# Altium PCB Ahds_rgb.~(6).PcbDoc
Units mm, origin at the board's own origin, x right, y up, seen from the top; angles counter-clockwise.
Board outline 51.94 x 97.28 mm, 2 copper layers (Top Layer, Bottom Layer); 73 components, 40 nets, 226 pads, 0 vias.
Unrouted connection lines stored in the file: 180.
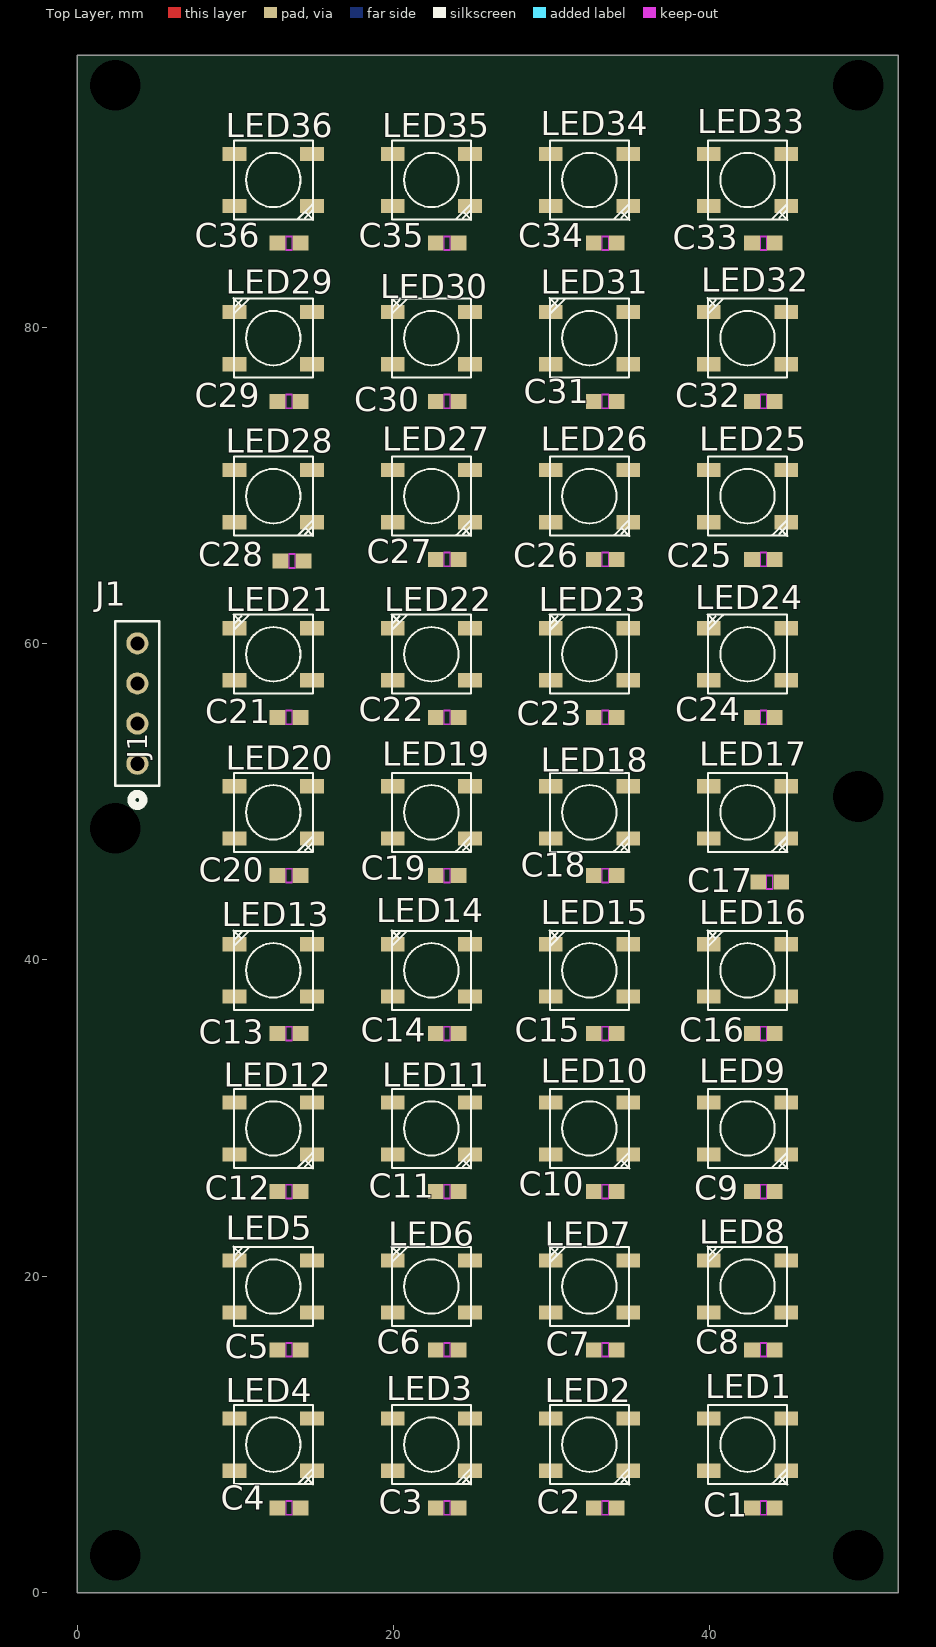
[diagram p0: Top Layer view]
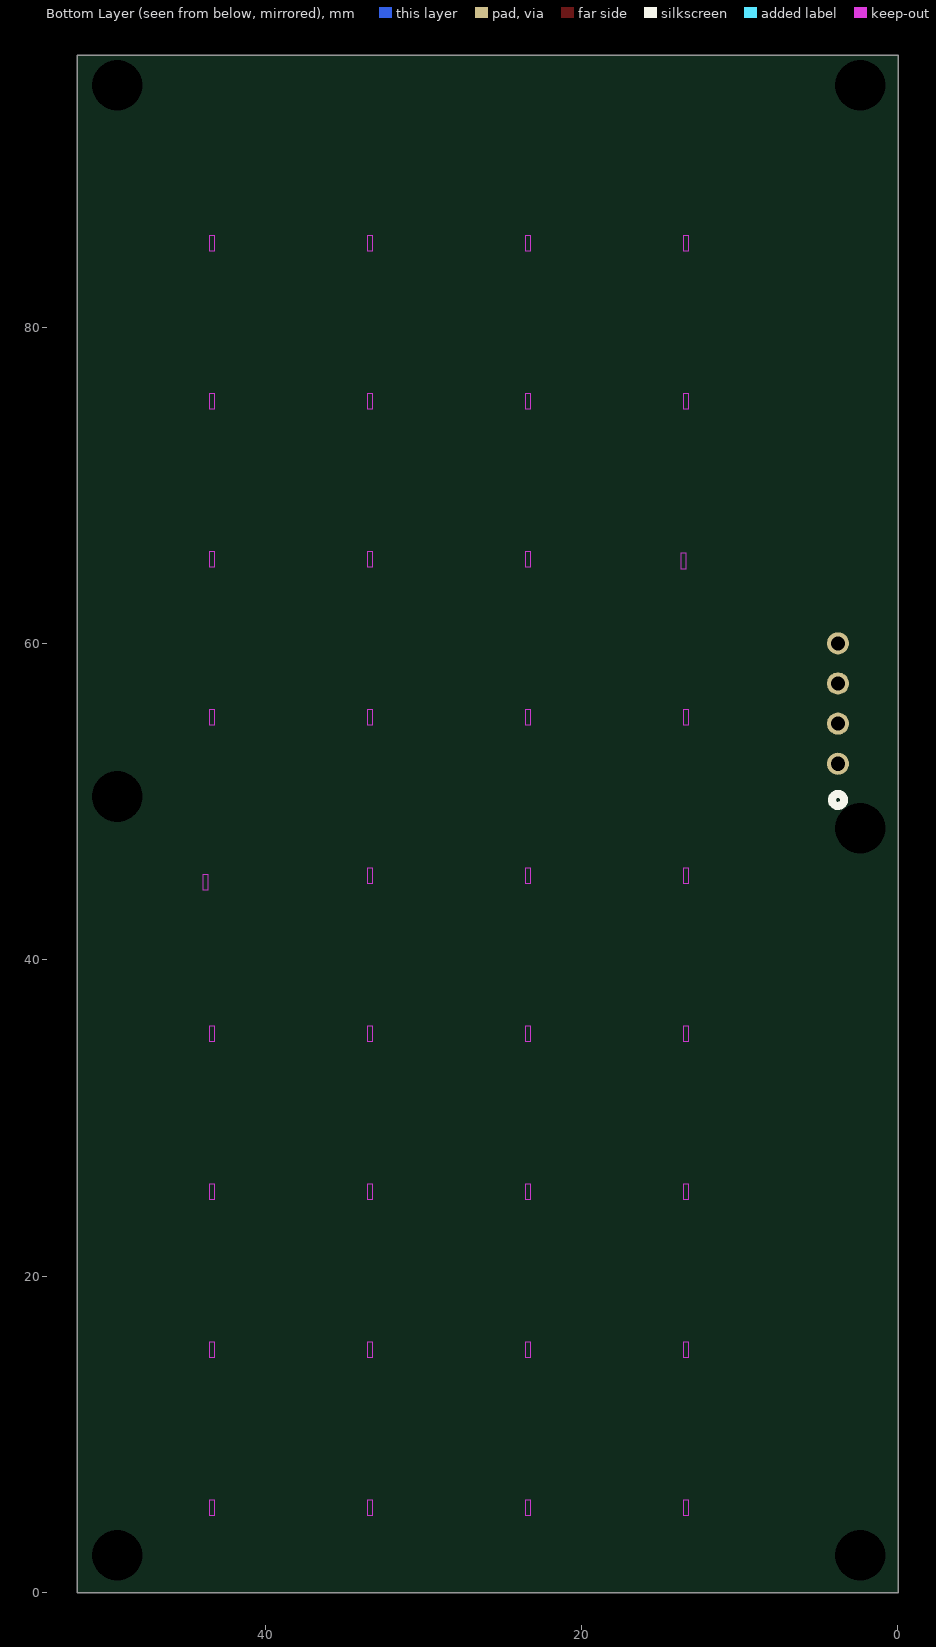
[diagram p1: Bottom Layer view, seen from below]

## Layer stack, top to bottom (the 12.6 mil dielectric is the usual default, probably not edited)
Top Solder: solder mask 0.0102, Solder Resist, Dk 3.5
Top Layer: signal copper 0.0356
Dielectric 1: dielectric 0.32, FR-4, Dk 4.8
Bottom Layer: signal copper 0.0356
Bottom Solder: solder mask 0.0102, Solder Resist, Dk 3.5

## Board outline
-0.018,-0.042 51.925,-0.042 51.925,97.24 -0.018,97.24

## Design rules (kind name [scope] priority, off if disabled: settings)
Clearance [All] p1: gap=0.254 ignorepadtopadclearanceinfootprint=FALSE
PolygonConnect [All] p1: connectstyle=Relief reliefconductorwidth=0.254 reliefentries=4 polygonreliefangle="90 Angle" airgapwidth=0.254
RoutingVias [All] p1: holewidth=0.711 width=1.27 viastyle="Through Hole" minholewidth=0.711 minwidth=1.27 maxholewidth=0.711 maxwidth=1.27
SolderMaskExpansion [All] p1: expansion=0.102 istentingtop=FALSE
Width [All] p1: maxlimit=0.254 minlimit=0.254 preferedwidth=0.254
30 further rules are at their usual default settings.

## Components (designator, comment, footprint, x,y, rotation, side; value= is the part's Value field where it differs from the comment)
C1 "100nF" CAPC17595_87N_KEM 43.393,5.339 r180 top
C2 "100nF" CAPC17595_87N_KEM 33.393,5.339 r180 top
C3 "100nF" CAPC17595_87N_KEM 23.393,5.339 r180 top
C4 "100nF" CAPC17595_87N_KEM 13.393,5.339 r180 top
C5 "100nF" CAPC17595_87N_KEM 13.393,15.339 r0 top
C6 "100nF" CAPC17595_87N_KEM 23.393,15.339 r0 top
C7 "100nF" CAPC17595_87N_KEM 33.393,15.339 r0 top
C8 "100nF" CAPC17595_87N_KEM 43.393,15.339 r0 top
C9 "100nF" CAPC17595_87N_KEM 43.393,25.339 r180 top
C10 "100nF" CAPC17595_87N_KEM 33.393,25.339 r180 top
C11 "100nF" CAPC17595_87N_KEM 23.393,25.339 r180 top
C12 "100nF" CAPC17595_87N_KEM 13.393,25.339 r180 top
C13 "100nF" CAPC17595_87N_KEM 13.393,35.339 r180 top
C14 "100nF" CAPC17595_87N_KEM 23.393,35.339 r0 top
C15 "100nF" CAPC17595_87N_KEM 33.393,35.339 r0 top
C16 "100nF" CAPC17595_87N_KEM 43.393,35.339 r0 top
C17 "100nF" CAPC17595_87N_KEM 43.797,44.916 r180 top
C18 "100nF" CAPC17595_87N_KEM 33.393,45.339 r180 top
C19 "100nF" CAPC17595_87N_KEM 23.393,45.339 r180 top
C20 "100nF" CAPC17595_87N_KEM 13.393,45.339 r180 top
C21 "100nF" CAPC17595_87N_KEM 13.393,55.339 r0 top
C22 "100nF" CAPC17595_87N_KEM 23.393,55.339 r0 top
C23 "100nF" CAPC17595_87N_KEM 33.393,55.339 r0 top
C24 "100nF" CAPC17595_87N_KEM 43.393,55.339 r0 top
C25 "100nF" CAPC17595_87N_KEM 43.393,65.339 r180 top
C26 "100nF" CAPC17595_87N_KEM 33.393,65.339 r180 top
C27 "100nF" CAPC17595_87N_KEM 23.393,65.339 r180 top
C28 "100nF" CAPC17595_87N_KEM 13.571,65.236 r180 top
C29 "100nF" CAPC17595_87N_KEM 13.393,75.339 r0 top
C30 "100nF" CAPC17595_87N_KEM 23.393,75.339 r0 top
C31 "100nF" CAPC17595_87N_KEM 33.393,75.339 r0 top
C32 "100nF" CAPC17595_87N_KEM 43.393,75.339 r0 top
C33 "100nF" CAPC17595_87N_KEM 43.393,85.339 r180 top
C34 "100nF" CAPC17595_87N_KEM 33.393,85.339 r180 top
C35 "100nF" CAPC17595_87N_KEM 23.393,85.339 r180 top
C36 "100nF" CAPC17595_87N_KEM 13.393,85.339 r180 top
J1 "901471304" CONN04_901471304_MOL 3.792,52.409 r90 top
LED1 "WS2812B" *WS2812B_WS2812B(Primary) 42.393,9.339 r0 top
LED2 "WS2812B" *WS2812B_WS2812B(Primary) 32.393,9.339 r0 top
LED3 "WS2812B" *WS2812B_WS2812B(Primary) 22.393,9.339 r0 top
LED4 "WS2812B" *WS2812B_WS2812B(Primary) 12.393,9.339 r0 top
LED5 "WS2812B" *WS2812B_WS2812B(Primary) 12.393,19.339 r180 top
LED6 "WS2812B" *WS2812B_WS2812B(Primary) 22.393,19.339 r180 top
LED7 "WS2812B" *WS2812B_WS2812B(Primary) 32.393,19.339 r180 top
LED8 "WS2812B" *WS2812B_WS2812B(Primary) 42.393,19.339 r180 top
LED9 "WS2812B" *WS2812B_WS2812B(Primary) 42.393,29.339 r0 top
LED10 "WS2812B" *WS2812B_WS2812B(Primary) 32.393,29.339 r0 top
LED11 "WS2812B" *WS2812B_WS2812B(Primary) 22.393,29.339 r0 top
LED12 "WS2812B" *WS2812B_WS2812B(Primary) 12.393,29.339 r0 top
LED13 "WS2812B" *WS2812B_WS2812B(Primary) 12.393,39.339 r180 top
LED14 "WS2812B" *WS2812B_WS2812B(Primary) 22.393,39.339 r180 top
LED15 "WS2812B" *WS2812B_WS2812B(Primary) 32.393,39.339 r180 top
LED16 "WS2812B" *WS2812B_WS2812B(Primary) 42.393,39.339 r180 top
LED17 "WS2812B" *WS2812B_WS2812B(Primary) 42.393,49.339 r0 top
LED18 "WS2812B" *WS2812B_WS2812B(Primary) 32.393,49.339 r0 top
LED19 "WS2812B" *WS2812B_WS2812B(Primary) 22.393,49.339 r0 top
LED20 "WS2812B" *WS2812B_WS2812B(Primary) 12.393,49.339 r0 top
LED21 "WS2812B" *WS2812B_WS2812B(Primary) 12.393,59.339 r180 top
LED22 "WS2812B" *WS2812B_WS2812B(Primary) 22.393,59.339 r180 top
LED23 "WS2812B" *WS2812B_WS2812B(Primary) 32.393,59.339 r180 top
LED24 "WS2812B" *WS2812B_WS2812B(Primary) 42.393,59.339 r180 top
LED25 "WS2812B" *WS2812B_WS2812B(Primary) 42.393,69.339 r0 top
LED26 "WS2812B" *WS2812B_WS2812B(Primary) 32.393,69.339 r0 top
LED27 "WS2812B" *WS2812B_WS2812B(Primary) 22.393,69.339 r0 top
LED28 "WS2812B" *WS2812B_WS2812B(Primary) 12.393,69.339 r0 top
LED29 "WS2812B" *WS2812B_WS2812B(Primary) 12.393,79.339 r180 top
LED30 "WS2812B" *WS2812B_WS2812B(Primary) 22.393,79.339 r180 top
LED31 "WS2812B" *WS2812B_WS2812B(Primary) 32.393,79.339 r180 top
LED32 "WS2812B" *WS2812B_WS2812B(Primary) 42.393,79.339 r180 top
LED33 "WS2812B" *WS2812B_WS2812B(Primary) 42.393,89.339 r0 top
LED34 "WS2812B" *WS2812B_WS2812B(Primary) 32.393,89.339 r0 top
LED35 "WS2812B" *WS2812B_WS2812B(Primary) 22.393,89.339 r0 top
LED36 "WS2812B" *WS2812B_WS2812B(Primary) 12.393,89.339 r0 top

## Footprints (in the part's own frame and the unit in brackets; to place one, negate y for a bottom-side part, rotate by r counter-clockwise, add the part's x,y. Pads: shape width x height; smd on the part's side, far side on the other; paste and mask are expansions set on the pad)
*WS2812B_WS2812B(Primary) [mm]
  rect 1.5x0.9 smd: 1(2.45,-1.65) 2(2.45,1.65) 3(-2.45,1.65) 4(-2.45,-1.65)
  silkscreen extent -2.5,-2.52 2.52,2.5
CAPC17595_87N_KEM [mm]
  rect 1x0.95 smd paste+0 mask+0: 1(-0.725,0) 2(0.725,0)
  Top Layer keep-out region: -0.174,-0.424 -0.174,0.424 0.174,0.424 0.174,-0.424
  Keep-Out Layer region: -0.174,-0.475 -0.174,0.475 0.174,0.475 0.174,-0.475
  body extent -0.87,-0.48 0.87,0.48, height 0.87
CONN04_901471304_MOL [mil]
  round 55 hole 35 paste-99999 mask+0: 1(0,0) 2(100,0) 3(200,0) 4(300,0)
  silkscreen extent -105,-55 355,55

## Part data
C1 C2 C3 C4 C5 C6 C7 C8 C9 C10 C11 C12 C13 C14 C15 C16 C17 C18 C19 C20 C21 C22 C23 C24 C25 C26 C27 C28 C29 C30 C31 C32 C33 C34 C35 C36: library part C0603C103K4RECTU, "ESD SMD Comm X7R, Ceramic, 0.01 uF, 10%, 16 VDC, X7R, SMD, MLCC, Temperature Stable, Electro Static Discharge, Class II, 0603", Manufacturer_Name=Kemet
J1: "C-Grid III PCB Receptacle, 2.54mm Pitch, Single Row, Vertical, Shrouded, 4 Circuits, 0.76Âµm Gold (Au) Plating", Manufacturer_Name=Molex
LED1 LED2 LED3 LED4 LED5 LED6 LED7 LED8 LED9 LED10 LED11 LED12 LED13 LED14 LED15 LED16 LED17 LED18 LED19 LED20 LED21 LED22 LED23 LED24 LED25 LED26 LED27 LED28 LED29 LED30 LED31 LED32 LED33 LED34 LED35 LED36: "Intelligent control LED integrated light source", Package=None

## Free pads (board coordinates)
  round 1.524 hole 3.2: 1(2.393,2.339) 2(49.393,2.339) 3(49.393,50.339) 4(49.393,95.339) 5(2.393,95.339) 6(2.393,48.339)

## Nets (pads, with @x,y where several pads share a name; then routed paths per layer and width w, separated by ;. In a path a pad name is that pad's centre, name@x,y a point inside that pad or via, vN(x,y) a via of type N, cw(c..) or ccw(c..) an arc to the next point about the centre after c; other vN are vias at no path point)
5V: C1.1 C2.1 C3.1 C4.1 C6.1 C7.1 C8.1 C9.1 C10.1 C11.1 C12.1 C13.1 C14.1 C15.1 C16.1 C17.1 C18.1 C19.1 C20.1 C21.1 C22.1 C23.1 C24.1 C25.1 C26.1 C27.1 C28.1 C29.1 C30.1 C31.1 C32.1 C33.1 C34.1 C35.1 C36.1 J1.1 LED1.1 LED2.1 LED3.1 LED4.1 LED6.1 LED7.1 LED8.1 LED9.1 LED10.1 LED11.1 LED12.1 LED13.1 LED14.1 LED15.1 LED16.1 LED17.1 LED18.1 LED19.1 LED20.1 LED21.1 LED22.1 LED23.1 LED24.1 LED25.1 LED26.1 LED27.1 LED28.1 LED29.1 LED30.1 LED31.1 LED32.1 LED33.1 LED34.1 LED35.1 LED36.1
GND: C1.2 C2.2 C3.2 C4.2 C5.2 C6.2 C7.2 C8.2 C9.2 C10.2 C11.2 C12.2 C13.2 C14.2 C15.2 C16.2 C17.2 C18.2 C19.2 C20.2 C21.2 C22.2 C23.2 C24.2 C25.2 C26.2 C27.2 C28.2 C29.2 C30.2 C31.2 C32.2 C33.2 C34.2 C35.2 C36.2 J1.4 LED1.3 LED2.3 LED3.3 LED4.3 LED5.3 LED6.3 LED7.3 LED8.3 LED9.3 LED10.3 LED11.3 LED12.3 LED13.3 LED14.3 LED15.3 LED16.3 LED17.3 LED18.3 LED19.3 LED20.3 LED21.3 LED22.3 LED23.3 LED24.3 LED25.3 LED26.3 LED27.3 LED28.3 LED29.3 LED30.3 LED31.3 LED32.3 LED33.3 LED34.3 LED35.3 LED36.3
NetC5_1: C5.1 LED5.1
NetJ1_2: J1.2 LED36.4
NetJ1_3: J1.3 LED1.2
NetLED1_4: LED1.4 LED2.2
NetLED2_4: LED2.4 LED3.2
NetLED3_4: LED3.4 LED4.2
NetLED4_4: LED4.4 LED5.2
NetLED5_4: LED5.4 LED6.2
NetLED6_4: LED6.4 LED7.2
NetLED7_4: LED7.4 LED8.2
NetLED8_4: LED8.4 LED9.2
NetLED9_4: LED9.4 LED10.2
NetLED10_4: LED10.4 LED11.2
NetLED11_4: LED11.4 LED12.2
NetLED12_4: LED12.4 LED13.2
NetLED13_4: LED13.4 LED14.2
NetLED14_4: LED14.4 LED15.2
NetLED15_4: LED15.4 LED16.2
NetLED16_4: LED16.4 LED17.2
NetLED17_4: LED17.4 LED18.2
NetLED18_4: LED18.4 LED19.2
NetLED19_4: LED19.4 LED20.2
NetLED20_4: LED20.4 LED21.2
NetLED21_4: LED21.4 LED22.2
NetLED22_4: LED22.4 LED23.2
NetLED23_4: LED23.4 LED24.2
NetLED24_4: LED24.4 LED25.2
NetLED25_4: LED25.4 LED26.2
NetLED26_4: LED26.4 LED27.2
NetLED27_4: LED27.4 LED28.2
NetLED28_4: LED28.4 LED29.2
NetLED29_4: LED29.4 LED30.2
NetLED30_4: LED30.4 LED31.2
NetLED31_4: LED31.4 LED32.2
NetLED32_4: LED32.4 LED33.2
NetLED33_4: LED33.4 LED34.2
NetLED34_4: LED34.4 LED35.2
NetLED35_4: LED35.4 LED36.2

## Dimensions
-0.018,-0.042 to -0.018,97.24 on Mechanical 1
-0.018,97.24 to 51.671,89.366 on Mechanical 1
